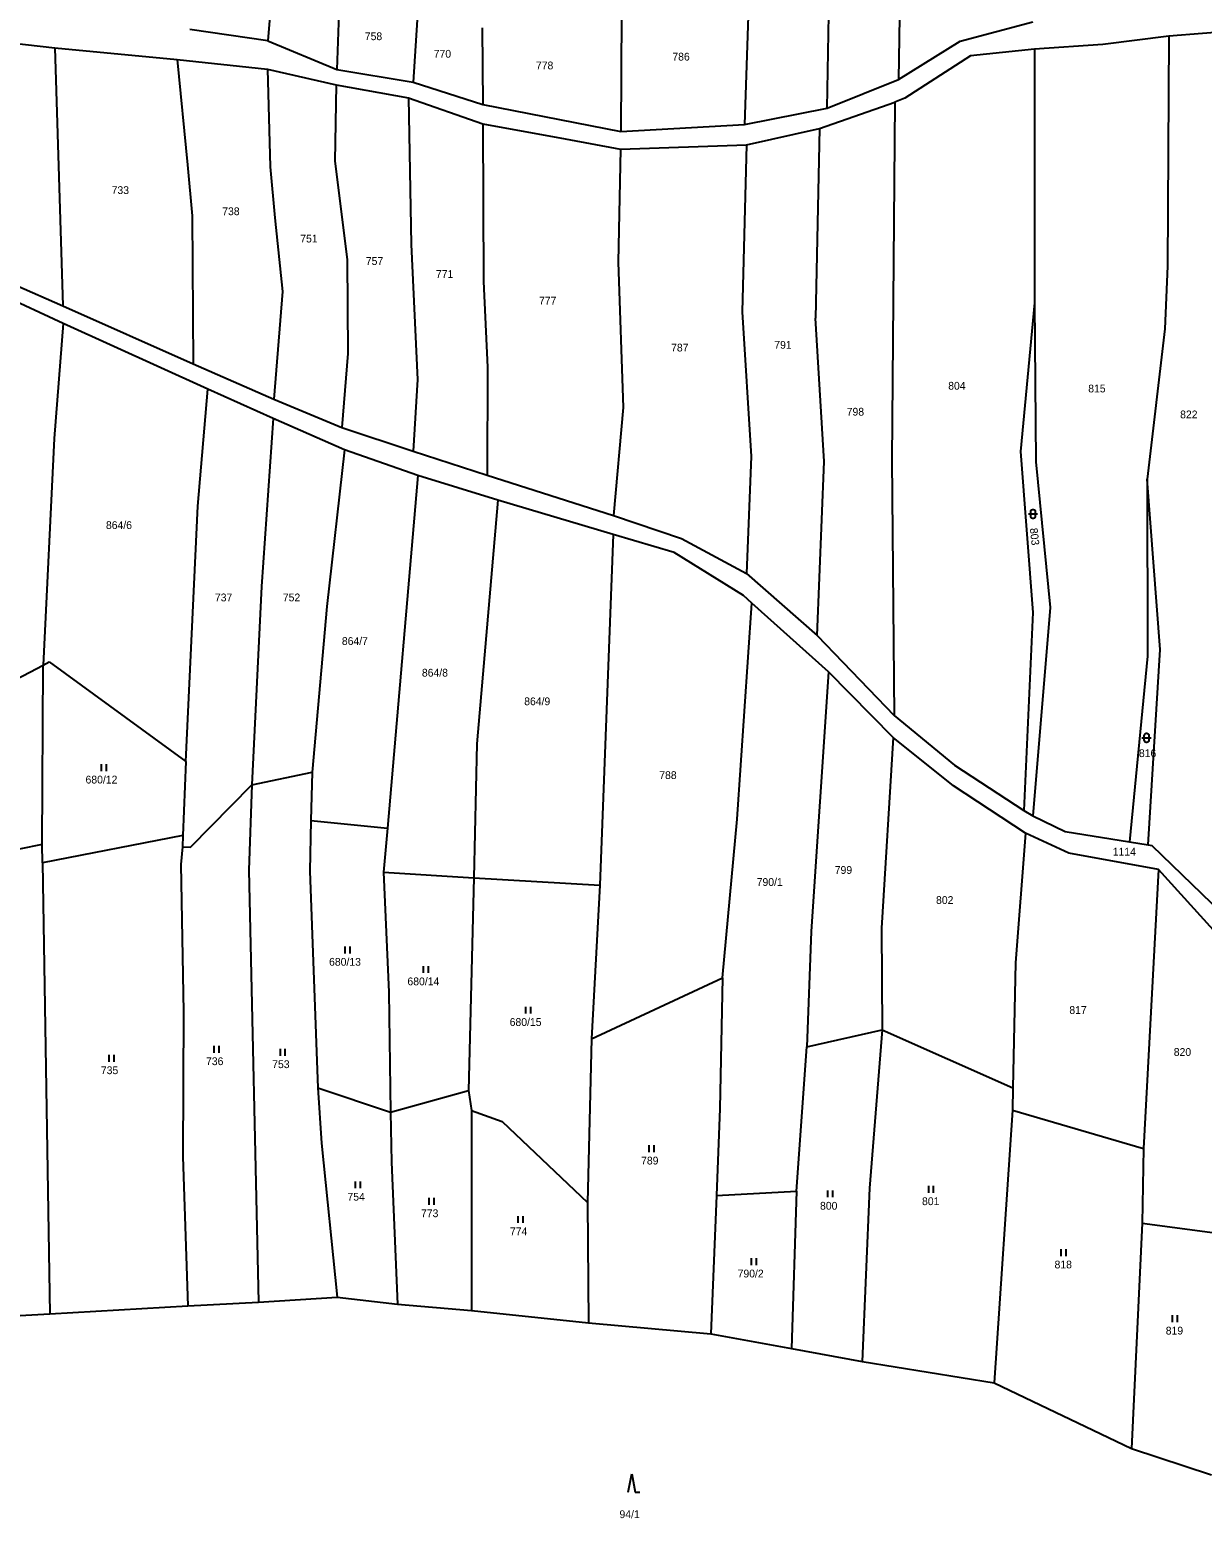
# Model space of a CAD drawing. Extents: x -794142 to -791199, y -1109267 to -1105626.
# Drawn here: x -793144.4 to -792888.4, y -1108415.2 to -1108090.1 of the extents above; entities that cross this region are included whole.
import ezdxf

# ---------------------------------------------------------------- set-up
doc = ezdxf.new("R2010")
doc.units = 0
for name, color, linetype in [('Vrstva 1', 7, 'Continuous'), ('Vrstva 14', 7, 'Continuous'), ('Vrstva 23', 7, 'Continuous')]:
    doc.layers.add(name, color=color, linetype=linetype)

msp = doc.modelspace()

# ---------------------------------------------------------------- linework, layer by layer
at = {"layer": 'Vrstva 1'}
for p, q in [((-793090.3, -1108067.09), (-793092.38, -1108092.56)), ((-792970.25, -1108107.25), (-792969.51, -1108067.95)), ((-792954.24, -1108069.6), (-792954.66, -1108101.01)), ((-792987.04, -1108074.22), (-792988.33, -1108110.78)), ((-793076.92, -1108086.54), (-793077.36, -1108098.79)), ((-793015.19, -1108086.54), (-793015.32, -1108112.34)), ((-793092.38, -1108092.56), (-793109.45, -1108090.07)), ((-793059.81, -1108087.93), (-793060.66, -1108101.58)), ((-793045.58, -1108089.73), (-793045.48, -1108106.43)), ((-792941.2, -1108092.64), (-792925.34, -1108088.37)), ((-792878.82, -1108090.18), (-792895.65, -1108091.52)), ((-793165.16, -1108091.03), (-793138.92, -1108094.06)), ((-793092.38, -1108092.56), (-793077.36, -1108098.79)), ((-792954.66, -1108101.01), (-792941.2, -1108092.64)), ((-792910.1, -1108093.31), (-792924.99, -1108094.35)), ((-792895.65, -1108091.52), (-792910.1, -1108093.31)), ((-792895.65, -1108091.52), (-792895.95, -1108141.74)), ((-793138.92, -1108094.06), (-793137.19, -1108150.39)), ((-793138.92, -1108094.06), (-793112.16, -1108096.64)), ((-793112.16, -1108096.64), (-793109.93, -1108119.59)), ((-793112.16, -1108096.64), (-793092.5, -1108098.73)), ((-792938.99, -1108095.84), (-792953.29, -1108105.08)), ((-792924.99, -1108094.35), (-792938.99, -1108095.84)), ((-792924.99, -1108094.35), (-792925.02, -1108149.78)), ((-793092.5, -1108098.73), (-793091.91, -1108120.04)), ((-793092.5, -1108098.73), (-793077.46, -1108102.16)), ((-793077.36, -1108098.79), (-793060.66, -1108101.58)), ((-793077.46, -1108102.16), (-793077.76, -1108118.85)), ((-793077.46, -1108102.16), (-793061.67, -1108104.99)), ((-793060.66, -1108101.58), (-793045.48, -1108106.43)), ((-792970.25, -1108107.25), (-792954.66, -1108101.01)), ((-793061.67, -1108104.99), (-793061.11, -1108137.03)), ((-793061.67, -1108104.99), (-793045.44, -1108110.65)), ((-793045.48, -1108106.43), (-793015.32, -1108112.34)), ((-792971.91, -1108111.67), (-792955.52, -1108105.97)), ((-792955.52, -1108105.97), (-792956.12, -1108184.05)), ((-792953.29, -1108105.08), (-792955.52, -1108105.97)), ((-792988.33, -1108110.78), (-792970.25, -1108107.25)), ((-793045.44, -1108110.65), (-793045.29, -1108145.07)), ((-793045.44, -1108110.65), (-793027.49, -1108113.93)), ((-793015.32, -1108112.34), (-792988.33, -1108110.78)), ((-792987.9, -1108115.24), (-792971.91, -1108111.67)), ((-792971.91, -1108111.67), (-792972.79, -1108153.15)), ((-793027.49, -1108113.93), (-793015.42, -1108116.17)), ((-793015.42, -1108116.17), (-793015.87, -1108140.9)), ((-793015.42, -1108116.17), (-792987.9, -1108115.24)), ((-792987.9, -1108115.24), (-792988.79, -1108151.75)), ((-793109.93, -1108119.59), (-793108.89, -1108130.77)), ((-793077.76, -1108118.85), (-793075.08, -1108140.3)), ((-793091.91, -1108120.04), (-793090.87, -1108131.21)), ((-793108.89, -1108130.77), (-793108.73, -1108163.07)), ((-793090.87, -1108131.21), (-793089.23, -1108147.31)), ((-793061.11, -1108137.03), (-793059.74, -1108166.53)), ((-793075.08, -1108140.3), (-793074.93, -1108160.86)), ((-793015.87, -1108140.9), (-793014.83, -1108172.64)), ((-792895.95, -1108141.74), (-792896.54, -1108155.44)), ((-793147.43, -1108145.9), (-793137.19, -1108150.39)), ((-793045.29, -1108145.07), (-793044.4, -1108163.85)), ((-793137.08, -1108154.29), (-793150.56, -1108148.05)), ((-793089.23, -1108147.31), (-793091.08, -1108170.77)), ((-793137.19, -1108150.39), (-793108.73, -1108163.07)), ((-792988.79, -1108151.75), (-792986.86, -1108183.34)), ((-792925.02, -1108149.78), (-792928.01, -1108182.22)), ((-792925.02, -1108149.78), (-792924.72, -1108184.52)), ((-793137.08, -1108154.29), (-793139.04, -1108179.38)), ((-793105.52, -1108168.62), (-793137.08, -1108154.29)), ((-792970.9, -1108184.42), (-792972.79, -1108153.15)), ((-792896.54, -1108155.44), (-792900.39, -1108188.29)), ((-793074.93, -1108160.86), (-793076.22, -1108177.02)), ((-793108.73, -1108163.07), (-793091.08, -1108170.77)), ((-793044.4, -1108163.85), (-793044.5, -1108187.41)), ((-793107.66, -1108194.19), (-793105.52, -1108168.62)), ((-793091.25, -1108175.04), (-793105.52, -1108168.62)), ((-793059.74, -1108166.53), (-793060.66, -1108182.14)), ((-793091.08, -1108170.77), (-793076.22, -1108177.02)), ((-793091.25, -1108175.04), (-793093.79, -1108211.69)), ((-793075.67, -1108181.87), (-793091.25, -1108175.04)), ((-793014.83, -1108172.64), (-793016.92, -1108196.18)), ((-793076.22, -1108177.02), (-793060.66, -1108182.14)), ((-793139.04, -1108179.38), (-793141.49, -1108228.9)), ((-793075.67, -1108181.87), (-793079.48, -1108216.06)), ((-793059.63, -1108187.47), (-793075.67, -1108181.87)), ((-793060.66, -1108182.14), (-793044.5, -1108187.41)), ((-792986.86, -1108183.34), (-792987.87, -1108208.91)), ((-792972.41, -1108222.45), (-792970.9, -1108184.42)), ((-792956.12, -1108184.05), (-792955.64, -1108239.91)), ((-792928.01, -1108182.22), (-792925.32, -1108217.38)), ((-792924.72, -1108184.52), (-792921.54, -1108216.28)), ((-793059.63, -1108187.47), (-793066.24, -1108264.52)), ((-793042.19, -1108192.88), (-793059.63, -1108187.47)), ((-793044.5, -1108187.41), (-793016.92, -1108196.18)), ((-792897.57, -1108225.46), (-792900.39, -1108188.29)), ((-792900.39, -1108188.29), (-792900.31, -1108226.94)), ((-793110.27, -1108249.97), (-793107.66, -1108194.19)), ((-793042.19, -1108192.88), (-793046.76, -1108246.06)), ((-793017, -1108200.37), (-793042.19, -1108192.88)), ((-793016.92, -1108196.18), (-793002.1, -1108201.26)), ((-793017, -1108200.37), (-793019.91, -1108276.96)), ((-793003.7, -1108204.33), (-793017, -1108200.37)), ((-792988.56, -1108213.72), (-793003.7, -1108204.33)), ((-793002.1, -1108201.26), (-792987.87, -1108208.91)), ((-792987.87, -1108208.91), (-792972.41, -1108222.45)), ((-793093.79, -1108211.69), (-793095.88, -1108255.01)), ((-792986.7, -1108215.38), (-792988.56, -1108213.72)), ((-793079.48, -1108216.06), (-793082.71, -1108252.27)), ((-792989.93, -1108262.56), (-792986.7, -1108215.38)), ((-792969.99, -1108230.34), (-792986.7, -1108215.38)), ((-792925.32, -1108217.38), (-792927.3, -1108260.65)), ((-792921.54, -1108216.28), (-792925.35, -1108261.82)), ((-792972.41, -1108222.45), (-792955.64, -1108239.91)), ((-792900.31, -1108226.94), (-792904.26, -1108267.5)), ((-792900.15, -1108268.17), (-792897.57, -1108225.46)), ((-793174.03, -1108245.91), (-793141.49, -1108228.9)), ((-793141.68, -1108268.04), (-793141.49, -1108228.9)), ((-793141.49, -1108228.9), (-793140.17, -1108228.21)), ((-793140.17, -1108228.21), (-793110.27, -1108249.97)), ((-792969.99, -1108230.34), (-792973.73, -1108287.07)), ((-792955.86, -1108244.71), (-792969.99, -1108230.34)), ((-792955.64, -1108239.91), (-792942.45, -1108250.76)), ((-793046.76, -1108246.06), (-793047.45, -1108275.32)), ((-792955.86, -1108244.71), (-792958.38, -1108286.37)), ((-792942.67, -1108255.25), (-792955.86, -1108244.71)), ((-793110.27, -1108249.97), (-793110.95, -1108266.1)), ((-793095.88, -1108255.01), (-793082.71, -1108252.27)), ((-793082.71, -1108252.27), (-793083, -1108262.86)), ((-792942.45, -1108250.76), (-792927.3, -1108260.65)), ((-793109.27, -1108268.63), (-793095.88, -1108255.01)), ((-793095.88, -1108255.01), (-793096.57, -1108273.65)), ((-792926.92, -1108265.59), (-792942.67, -1108255.25)), ((-793083, -1108262.86), (-793083.26, -1108273.91)), ((-793083, -1108262.86), (-793066.24, -1108264.52)), ((-792993.12, -1108297.17), (-792989.93, -1108262.56)), ((-792927.3, -1108260.65), (-792925.35, -1108261.82)), ((-792925.35, -1108261.82), (-792918.32, -1108265.23)), ((-793110.95, -1108266.1), (-793141.58, -1108272.05)), ((-793110.95, -1108266.1), (-793111.05, -1108268.56)), ((-793066.24, -1108264.52), (-793067.13, -1108274.15)), ((-792926.92, -1108265.59), (-792929.17, -1108293.93)), ((-792917.51, -1108269.94), (-792926.92, -1108265.59)), ((-792918.32, -1108265.23), (-792904.26, -1108267.5)), ((-793141.68, -1108268.04), (-793173.67, -1108274.6)), ((-793141.58, -1108272.05), (-793141.68, -1108268.04)), ((-793111.05, -1108268.56), (-793111.38, -1108272.45)), ((-793111.05, -1108268.56), (-793109.27, -1108268.63)), ((-792904.26, -1108267.5), (-792900.15, -1108268.17)), ((-792900.15, -1108268.17), (-792899.4, -1108268.29)), ((-792899.4, -1108268.29), (-792881.96, -1108285.08)), ((-793141.58, -1108272.05), (-793140.02, -1108370.58)), ((-793111.38, -1108272.45), (-793110.78, -1108304.65)), ((-792897.89, -1108273.53), (-792917.51, -1108269.94)), ((-793096.57, -1108273.65), (-793094.46, -1108368.05)), ((-793083.26, -1108273.91), (-793081.47, -1108321.22)), ((-793067.13, -1108274.15), (-793065.97, -1108300.29)), ((-793067.13, -1108274.15), (-793047.45, -1108275.32)), ((-793047.45, -1108275.32), (-793048.55, -1108321.79)), ((-793047.45, -1108275.32), (-793019.91, -1108276.96)), ((-792897.89, -1108273.53), (-792901.17, -1108334.49)), ((-792880.81, -1108292.42), (-792897.89, -1108273.53)), ((-793019.91, -1108276.96), (-793021.69, -1108310.5)), ((-792973.73, -1108287.07), (-792974.69, -1108312.28)), ((-792958.38, -1108286.37), (-792958.26, -1108308.58)), ((-792929.17, -1108293.93), (-792929.73, -1108321.24)), ((-793021.69, -1108310.5), (-792993.12, -1108297.17)), ((-792993.12, -1108297.17), (-792993.71, -1108325.75)), ((-793065.97, -1108300.29), (-793065.58, -1108326.53)), ((-793110.78, -1108304.65), (-793110.98, -1108336.26)), ((-793021.69, -1108310.5), (-793022.57, -1108346.25)), ((-792974.69, -1108312.28), (-792958.26, -1108308.58)), ((-792958.26, -1108308.58), (-792961.03, -1108343.16)), ((-792958.26, -1108308.58), (-792929.73, -1108321.24)), ((-792976.99, -1108343.82), (-792974.69, -1108312.28)), ((-793081.47, -1108321.22), (-793080.68, -1108333.28)), ((-793081.47, -1108321.22), (-793065.58, -1108326.53)), ((-792929.73, -1108321.24), (-792929.81, -1108326.12)), ((-793065.58, -1108326.53), (-793048.55, -1108321.79)), ((-793048.55, -1108321.79), (-793047.95, -1108326.17)), ((-793065.58, -1108326.53), (-793065.38, -1108337.46)), ((-793047.95, -1108326.17), (-793047.9, -1108369.88)), ((-793047.95, -1108326.17), (-793041.2, -1108328.55)), ((-792993.71, -1108325.75), (-792994.45, -1108344.71)), ((-792929.81, -1108326.12), (-792933.83, -1108385.66)), ((-792929.81, -1108326.12), (-792901.17, -1108334.49)), ((-793041.2, -1108328.55), (-793022.57, -1108346.25)), ((-793080.68, -1108333.28), (-793077.27, -1108366.93)), ((-793110.98, -1108336.26), (-793109.88, -1108368.86)), ((-793065.38, -1108337.46), (-793064.07, -1108368.46)), ((-792901.17, -1108334.49), (-792901.5, -1108350.78)), ((-792994.45, -1108344.71), (-792976.99, -1108343.82)), ((-792976.99, -1108343.82), (-792978.05, -1108378.13)), ((-792961.03, -1108343.16), (-792962.59, -1108380.98)), ((-793022.57, -1108346.25), (-793022.36, -1108372.53)), ((-792994.45, -1108344.71), (-792995.65, -1108374.97)), ((-792901.5, -1108350.78), (-792903.82, -1108400.01)), ((-792901.5, -1108350.78), (-792883.44, -1108353.15)), ((-793094.46, -1108368.05), (-793077.27, -1108366.93)), ((-793077.27, -1108366.93), (-793064.07, -1108368.46)), ((-793140.02, -1108370.58), (-793109.88, -1108368.86)), ((-793109.88, -1108368.86), (-793094.46, -1108368.05)), ((-793064.07, -1108368.46), (-793047.9, -1108369.88)), ((-793047.9, -1108369.88), (-793022.36, -1108372.53)), ((-793172.29, -1108372.43), (-793140.02, -1108370.58)), ((-793022.36, -1108372.53), (-792995.65, -1108374.97)), ((-792995.65, -1108374.97), (-792978.05, -1108378.13)), ((-792978.05, -1108378.13), (-792962.59, -1108380.98)), ((-792962.59, -1108380.98), (-792933.83, -1108385.66)), ((-792933.83, -1108385.66), (-792903.82, -1108400.01)), ((-792903.82, -1108400.01), (-792886.32, -1108405.71))]:
    msp.add_line(p, q, dxfattribs=at)
at = {"layer": 'Vrstva 23'}
for p, q in [((-792926.32, -1108195.87), (-792924.32, -1108195.87)), ((-792925.82, -1108195.27), (-792925.72, -1108195.07)), ((-792925.82, -1108196.47), (-792925.82, -1108195.27)), ((-792925.72, -1108196.67), (-792925.82, -1108196.47)), ((-792925.72, -1108195.07), (-792925.62, -1108194.97)), ((-792925.62, -1108196.77), (-792925.72, -1108196.67)), ((-792925.62, -1108194.97), (-792925.42, -1108194.87)), ((-792925.42, -1108196.87), (-792925.62, -1108196.77)), ((-792925.42, -1108194.87), (-792925.22, -1108194.87)), ((-792925.22, -1108196.87), (-792925.42, -1108196.87)), ((-792925.22, -1108194.87), (-792925.02, -1108194.97)), ((-792925.02, -1108196.77), (-792925.22, -1108196.87)), ((-792925.02, -1108194.97), (-792924.92, -1108195.07)), ((-792924.92, -1108196.67), (-792925.02, -1108196.77)), ((-792924.92, -1108195.07), (-792924.82, -1108195.27)), ((-792924.82, -1108196.47), (-792924.92, -1108196.67)), ((-792924.82, -1108195.27), (-792924.82, -1108196.47)), ((-792901.53, -1108244.79), (-792899.53, -1108244.79)), ((-792901.03, -1108244.19), (-792900.93, -1108243.99)), ((-792901.03, -1108245.39), (-792901.03, -1108244.19)), ((-792900.93, -1108245.59), (-792901.03, -1108245.39)), ((-792900.93, -1108243.99), (-792900.83, -1108243.89)), ((-792900.83, -1108245.69), (-792900.93, -1108245.59)), ((-792900.83, -1108243.89), (-792900.63, -1108243.79)), ((-792900.63, -1108245.79), (-792900.83, -1108245.69)), ((-792900.63, -1108243.79), (-792900.43, -1108243.79)), ((-792900.43, -1108245.79), (-792900.63, -1108245.79)), ((-792900.43, -1108243.79), (-792900.23, -1108243.89)), ((-792900.23, -1108245.69), (-792900.43, -1108245.79)), ((-792900.23, -1108243.89), (-792900.13, -1108243.99)), ((-792900.13, -1108245.59), (-792900.23, -1108245.69)), ((-792900.13, -1108243.99), (-792900.03, -1108244.19)), ((-792900.03, -1108245.39), (-792900.13, -1108245.59)), ((-792900.03, -1108244.19), (-792900.03, -1108245.39)), ((-793128.71, -1108252.05), (-793128.71, -1108250.55)), ((-793127.71, -1108250.55), (-793127.71, -1108252.05)), ((-793075.51, -1108291.85), (-793075.51, -1108290.35)), ((-793074.51, -1108290.35), (-793074.51, -1108291.85)), ((-793058.42, -1108296.12), (-793058.42, -1108294.62)), ((-793057.42, -1108294.62), (-793057.42, -1108296.12)), ((-793036.06, -1108305), (-793036.06, -1108303.5)), ((-793035.06, -1108303.5), (-793035.06, -1108305)), ((-793127.06, -1108315.53), (-793127.06, -1108314.03)), ((-793126.06, -1108314.03), (-793126.06, -1108315.53)), ((-793104.12, -1108313.56), (-793104.12, -1108312.06)), ((-793103.12, -1108312.06), (-793103.12, -1108313.56)), ((-793089.65, -1108314.21), (-793089.65, -1108312.71)), ((-793088.65, -1108312.71), (-793088.65, -1108314.21)), ((-793009.14, -1108335.26), (-793009.14, -1108333.76)), ((-793008.14, -1108333.76), (-793008.14, -1108335.26)), ((-793073.25, -1108343.16), (-793073.25, -1108341.66)), ((-793072.25, -1108341.66), (-793072.25, -1108343.16)), ((-792970.12, -1108345.13), (-792970.12, -1108343.63)), ((-792969.12, -1108343.63), (-792969.12, -1108345.13)), ((-792948.09, -1108344.14), (-792948.09, -1108342.64)), ((-792947.09, -1108342.64), (-792947.09, -1108344.14)), ((-793057.14, -1108346.77), (-793057.14, -1108345.27)), ((-793056.14, -1108345.27), (-793056.14, -1108346.77)), ((-793037.74, -1108350.72), (-793037.74, -1108349.22)), ((-793036.74, -1108349.22), (-793036.74, -1108350.72)), ((-792919.16, -1108357.96), (-792919.16, -1108356.46)), ((-792918.16, -1108356.46), (-792918.16, -1108357.96)), ((-792986.78, -1108359.93), (-792986.78, -1108358.43)), ((-792985.78, -1108358.43), (-792985.78, -1108359.93)), ((-792894.86, -1108372.4), (-792894.86, -1108370.9)), ((-792893.86, -1108370.9), (-792893.86, -1108372.4)), ((-793013.75, -1108409.5), (-793012.95, -1108405.5)), ((-793012.95, -1108405.5), (-793012.15, -1108409.5)), ((-793012.15, -1108409.5), (-793011.15, -1108409.5))]:
    msp.add_line(p, q, dxfattribs=at)

# ---------------------------------------------------------------- texts
at = {"layer": 'Vrstva 14'}
for s, p in [('758', (-793071.219, -1108092.39)), ('770', (-793056.169, -1108096.22)), ('778', (-793033.85, -1108098.77)), ('786', (-793004.063, -1108096.85)), ('733', (-793126.503, -1108126)), ('738', (-793102.353, -1108130.62)), ('751', (-793085.313, -1108136.58)), ('757', (-793070.996, -1108141.49)), ('771', (-793055.693, -1108144.33)), ('777', (-793033.186, -1108150.14)), ('787', (-793004.34, -1108160.39)), ('791', (-792981.807, -1108159.79)), ('804', (-792943.832, -1108168.73)), ('815', (-792913.256, -1108169.33)), ('798', (-792965.993, -1108174.4)), ('822', (-792893.186, -1108174.99)), ('864/6', (-793127.746, -1108199.17)), ('737', (-793103.95, -1108214.96)), ('752', (-793089.119, -1108214.96)), ('864/7', (-793076.232, -1108224.49)), ('864/8', (-793058.755, -1108231.4)), ('864/9', (-793036.416, -1108237.65)), ('816', (-792902.19, -1108248.98)), ('680/12', (-793132.202, -1108254.75)), ('788', (-793006.923, -1108253.77)), ('1114', (-792907.91, -1108270.5)), ('790/1', (-792985.649, -1108277.12)), ('799', (-792968.603, -1108274.49)), ('802', (-792946.486, -1108281.06)), ('680/13', (-793079.022, -1108294.55)), ('680/14', (-793061.908, -1108298.82)), ('817', (-792917.376, -1108305.07)), ('680/15', (-793039.588, -1108307.7)), ('736', (-793105.893, -1108316.26)), ('820', (-792894.576, -1108314.25)), ('735', (-793128.85, -1108318.23)), ('753', (-793091.44, -1108316.91)), ('789', (-793010.893, -1108337.96)), ('754', (-793075.015, -1108345.86)), ('800', (-792971.815, -1108347.83)), ('801', (-792949.549, -1108346.84)), ('773', (-793058.95, -1108349.47)), ('774', (-793039.526, -1108353.42)), ('818', (-792920.61, -1108360.66)), ('790/2', (-792989.816, -1108362.63)), ('819', (-792896.33, -1108375.1)), ('94/1', (-793015.609, -1108415.2))]:
    msp.add_text(s, height=1.7, dxfattribs=at).set_placement(p)
msp.add_text('803', height=1.7, rotation=276.37245, dxfattribs=at).set_placement((-792926.019, -1108199.038))

doc.saveas('drawing.dxf')
